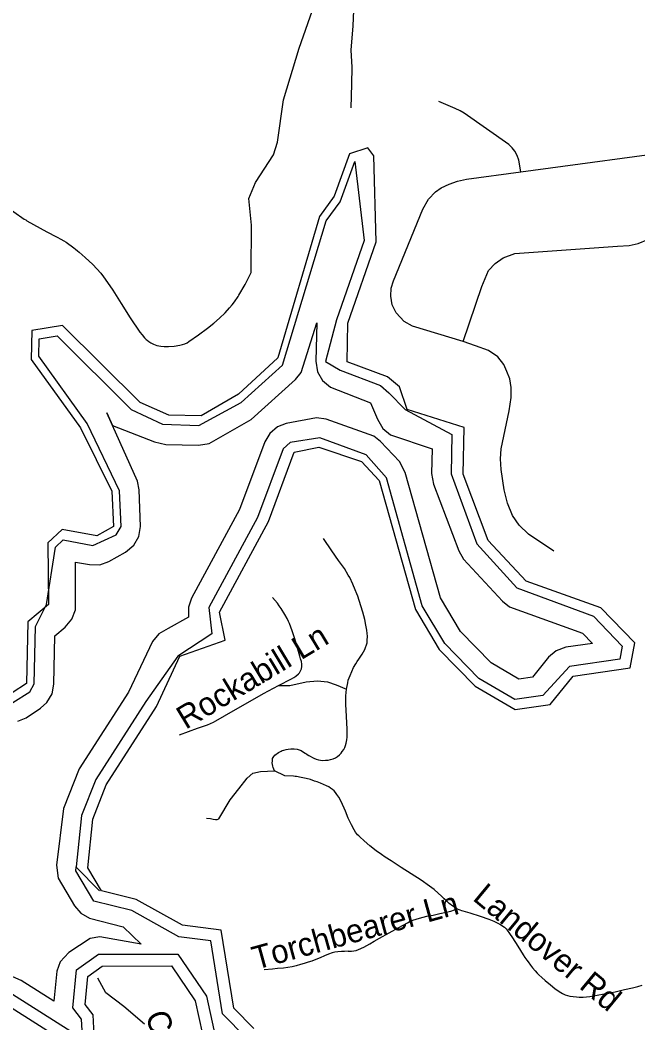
# Model space of a CAD drawing. Extents: x 1383679 to 1536984, y 460658 to 651027.
# Drawn here: x 1388732 to 1391260, y 481592 to 485692 of the extents above; entities that cross this region are included whole.
import ezdxf

# ---------------------------------------------------------------- set-up
doc = ezdxf.new("R2010")
doc.units = 0
for name, color, linetype in [('Exist Hydrographic Bay Label', 7, 'Continuous'), ('Exist Hydrographic Buffer Line', 7, 'Continuous'), ('Exist Hydrographic Misc Water Feature', 7, 'Continuous'), ('Exist Road Non-System Type 51', 7, 'Continuous'), ('Exist Road Non-System Type 51 Label', 7, 'Continuous')]:
    doc.layers.add(name, color=color, linetype=linetype)

msp = doc.modelspace()

# ---------------------------------------------------------------- linework, layer by layer
at = {"layer": 'Exist Hydrographic Bay Label'}
for points in [[(1389688.1, 481568.7), (1389606.1, 481652.4), (1389555.2, 481971.8), (1389397.2, 481991.4), (1389207.2, 482096.9), (1389066.1, 482132.6), (1389010.2, 482225.7), (1389030.2, 482425.5), (1389084.2, 482565.5), (1389290.2, 482886.3), (1389386.2, 483091.2), (1389571.2, 483156.5), (1389548.2, 483271.8), (1389748.1, 483642), (1389854.1, 483925.4), (1389954.1, 483946.4), (1390128.2, 483887.1), (1390201.1, 483810.2), (1390349.1, 483282), (1390446.1, 483119.2), (1390593.1, 482968.5), (1390757.1, 482873.4), (1390900.1, 482893.5), (1390994.1, 483009.7), (1391228, 483044.4), (1391247, 483145.8), (1391108.1, 483289.7), (1390802.1, 483397.7), (1390647.1, 483564.9), (1390544.1, 483836.1), (1390548.1, 484026.4), (1390316.1, 484100), (1390284.1, 484192.5), (1390235.1, 484232.8), (1390070.2, 484295.3), (1390073.1, 484452.8), (1390189.2, 484785.3), (1390179.1, 485136.6), (1390155.2, 485170), (1390079.2, 485145.2), (1390017.2, 484972.5), (1389957.2, 484888.4), (1389787.2, 484310.8), (1389625.2, 484163), (1389473.2, 484074.2), (1389340.2, 484076.9), (1389224.2, 484128.5), (1388906.2, 484443.3), (1388780.2, 484422.9), (1388778.3, 484304.8), (1388980.2, 484025), (1389108.2, 483766.4)], [(1389108.2, 483766.4), (1389114.2, 483621.9), (1389046.2, 483583.8), (1388905.2, 483609.7), (1388846.2, 483555), (1388849.2, 483302.2), (1388764.2, 483231.7), (1388759.2, 482979.1), (1388700.3, 482940.9)], [(1389037.2, 481516.1), (1389031.2, 481624.5), (1388998.2, 481667.8), (1389009.1, 481782.5), (1389068.2, 481824), (1389352.2, 481824.8), (1389449.2, 481681.8), (1389479.1, 481546.5)], [(1387736.3, 481525.7), (1387771.3, 481607.1), (1387924.3, 481722.2), (1388482.2, 481717.6), (1388681.2, 481664.4), (1388928.2, 481508.4)]]:
    msp.add_lwpolyline(points, dxfattribs=at)
at = {"layer": 'Exist Hydrographic Buffer Line'}
msp.add_line((1388961.7, 482229.5), (1389057.5, 482132.5), dxfattribs=at)
for points in [[(1388702.2, 482902.2), (1388772.2, 482945.4), (1388790.5, 482978.1), (1388795.2, 483212.5), (1388840.5, 483302.1), (1388877.7, 483537.6), (1388909, 483566.6), (1389030.3, 483544.3), (1389125, 483586.8), (1389145.5, 483621.7), (1389139.5, 483768), (1389007.4, 484042.6), (1388809.8, 484317.3), (1388811, 484388.6), (1388883.9, 484400.5), (1389187.4, 484099.9), (1389315.2, 484040.2), (1389463.7, 484034.1), (1389636.7, 484128.3), (1389805.5, 484281.1), (1389985, 484870.5), (1390041.1, 484949.1), (1390101.6, 485113.1), (1390140.3, 484791.3), (1390026.7, 484465.8), (1389981.5, 484296.6), (1390041.5, 484260.4), (1390206.2, 484197.6), (1390241.3, 484168.6), (1390307.5, 484099.8), (1390498.9, 483997.1), (1390495.5, 483836.7), (1390601, 483550.5), (1390764.1, 483370.3), (1391077.2, 483254.9), (1391195.2, 483132.7), (1391185.4, 483079.6), (1390979.6, 483049.1), (1390870.2, 482930.7), (1390756.5, 482914.7), (1390609.3, 483000.2), (1390469.5, 483143.6), (1390377.6, 483297.7), (1390231, 483820.8), (1390148.5, 483914.5), (1389958.4, 483984.1), (1389837.3, 483964.4), (1389808.1, 483939.3), (1389703, 483658.5), (1389504.4, 483290.6), (1389516.5, 483182.5), (1389377.6, 483091.1), (1389246.4, 482905.6), (1389041.9, 482587.1), (1388984.2, 482439.8), (1388961.7, 482229.6)], [(1389087.3, 484086.4), (1389110.8, 484034), (1389282.7, 483967.1), (1389329.2, 483956.8), (1389462.1, 483954.1), (1389505.5, 483961.3), (1389677, 484059.3), (1389859.4, 484222), (1389882.5, 484250.7), (1389945.8, 484454.5), (1389941.5, 484297.3), (1389948.7, 484254), (1389969.5, 484217.9), (1390001.5, 484191.2), (1390165.5, 484127.4), (1390194.1, 484060.6), (1390215.5, 484022.6), (1390247.5, 483995.9), (1390417.6, 483938.9), (1390415.5, 483838.4), (1390422.7, 483794.8), (1390526.3, 483522.1), (1390546.5, 483487.5), (1390705.5, 483315.9), (1390733.5, 483293.6), (1391032.8, 483185.8), (1391073.3, 483143.9), (1390964.7, 483127.7), (1390925.5, 483113.4), (1390893.5, 483086.7), (1390827.9, 483005.5), (1390772.8, 482997.8), (1390658.9, 483063.9), (1390533.3, 483192.6), (1390451.7, 483329.5), (1390308, 483842.4), (1390284.4, 483887.1), (1390206.7, 483969.5), (1390179.5, 483990.8), (1389984.1, 484059.8), (1389945.4, 484066.2), (1389820.9, 484042.7), (1389785.5, 484029.2), (1389753.5, 484002.4), (1389733.1, 483967.3), (1389630, 483691.6), (1389433.9, 483328.6), (1389421.3, 483292.4), (1389421.3, 483250.8), (1389337.7, 483204.2), (1389300.5, 483183), (1389273.6, 483151), (1389176.2, 482944.3), (1388974.5, 482630.3), (1388909.5, 482468.6), (1388882, 482237.5), (1388888.7, 482184.5), (1388954.6, 482070.6), (1388980.4, 482040.5), (1389016.5, 482019.7), (1389153.9, 481984.3), (1389227.6, 481914), (1389059.2, 481943.9), (1389018.5, 481936.7), (1388931.5, 481880.6), (1388896.5, 481842.4), (1388882.2, 481803.2), (1388870.3, 481681.3), (1388736.6, 481765.7), (1388703.5, 481780.2)], [(1388958.7, 483281.3), (1388958.5, 483476.2), (1389015.8, 483465.7), (1389058.3, 483465.5), (1389096, 483478.9), (1389164.1, 483517), (1389197.5, 483544.6), (1389218.3, 483580.7), (1389225.5, 483621.7), (1389219.4, 483771.3), (1389212.3, 483807.4), (1389110.8, 484034), (1389087.3, 484086.4)], [(1388723.5, 482825.1), (1388756.8, 482840), (1388815.7, 482878.2), (1388842.5, 482901.8), (1388863.3, 482937.9), (1388870.5, 482976.6), (1388874.5, 483174.3), (1388917.1, 483209.7), (1388944.5, 483242.1), (1388958.7, 483281.3)], [(1389658.3, 481529.7), (1389560.6, 481629.5), (1389512.9, 481928.1), (1389381.8, 481944.3), (1389189.2, 482051.3), (1389034.8, 482090.3), (1388960.2, 482214.4), (1388961.7, 482229.6)], [(1388986, 481561.2), (1388983.5, 481606.9), (1388948, 481653.5), (1388962.9, 481809.5), (1389052.8, 481872.6), (1389377.9, 481873.5), (1389494.6, 481701.4), (1389525, 481564.3)], [(1387688.4, 481537.4), (1387731.7, 481638.2), (1387908.2, 481770.9), (1388488.8, 481766.2), (1388700.9, 481709.4), (1388940.6, 481558)]]:
    msp.add_lwpolyline(points, dxfattribs=at)
at = {"layer": 'Exist Hydrographic Misc Water Feature'}
msp.add_lwpolyline([(1390240.9, 486340.5), (1390239.6, 486276.6), (1390238.9, 486240.5), (1390251.7, 486186), (1390260.5, 486130), (1390266.1, 486106.2), (1390254.9, 486046.5), (1390217.7, 485990.6), (1390158.1, 485917.9), (1390110.7, 485853.2), (1390099.5, 485793.6), (1390092.9, 485669), (1390084.8, 485569), (1390089.4, 485499.2), (1390088, 485429.4), (1390085.9, 485333.5)], dxfattribs=at)
at = {"layer": 'Exist Road Non-System Type 51'}
for points in [[(1388664, 484937.4), (1388749.5, 484878.4), (1388755.9, 484874.6), (1388760.5, 484871.6), (1388841.6, 484826.8), (1388881.4, 484805.6), (1388883.8, 484804.4), (1388899, 484796.6), (1388911.1, 484789.4), (1388920.3, 484783.6), (1388952.8, 484761.2), (1388959.4, 484755.8), (1388967.4, 484748.9), (1388973.8, 484743.4), (1388999, 484721.6), (1389029.7, 484692.1), (1389062.1, 484657), (1389065.1, 484653.6), (1389070.5, 484646), (1389112, 484587.1), (1389145.9, 484533.6), (1389183.3, 484475.2), (1389222.6, 484416.4), (1389231.8, 484404.9), (1389242, 484393), (1389244.6, 484389.8), (1389248.2, 484386.2), (1389252.1, 484382.7), (1389258.7, 484377.6), (1389266.7, 484372.6), (1389277.8, 484367.3), (1389291.8, 484362), (1389307.5, 484358.4), (1389321.3, 484357.2), (1389339.4, 484357.3), (1389363, 484359.3), (1389386.2, 484362.7), (1389396.5, 484365.3), (1389406.8, 484368.9), (1389415.9, 484373), (1389422.9, 484377.2), (1389462.1, 484405.3), (1389499.1, 484432.1), (1389524.4, 484452.5), (1389548.5, 484473), (1389570.6, 484494.5), (1389589.3, 484515.3), (1389600, 484528.2), (1389609.5, 484540.2), (1389624, 484561.2), (1389627.7, 484567.2), (1389652.5, 484611.4), (1389677.6, 484659.9), (1389679.2, 484854.1), (1389668, 484962.4), (1389695.9, 485027.4), (1389768.5, 485141.2), (1389785.3, 485192.6), (1389810.4, 485365.9), (1389874.6, 485577.1), (1389936, 485755.9)], [(1390779.9, 485071.1), (1390772.4, 485119.7), (1390765.6, 485138.9), (1390756, 485156), (1390745.6, 485170.1), (1390731.5, 485183.5), (1390548.1, 485311.2), (1390532.6, 485320.8), (1390511.8, 485330.4), (1390445.8, 485358.7)], [(1390779.9, 485071.1), (1391487.6, 485167.5), (1391529, 485169.7), (1391561.8, 485160.9), (1391603.2, 485130.3)], [(1390545, 484377.7), (1390621.4, 484602.3), (1390647.6, 484667.8), (1390675.9, 484696.2), (1390708.6, 484720.2), (1390756.6, 484737.7), (1391175.6, 484768.2), (1391223.6, 484770.3), (1391260.6, 484779.1), (1391299.9, 484794.3), (1391334.9, 484824.9), (1391603.2, 485130.3)], [(1390545, 484377.7), (1390337.8, 484440.9), (1390303.1, 484460.3), (1390270.1, 484495.5), (1390254.9, 484528.2), (1390248.4, 484563.1), (1390250.5, 484595.8), (1390259.2, 484626.3), (1390379.2, 484918.8), (1390403.4, 484960), (1390431.2, 484989.1), (1390454.6, 485006.6), (1390487.1, 485020.6), (1390522.1, 485033.4), (1390558.1, 485040.9), (1390779.9, 485071.1)], [(1390915.9, 483520.2), (1390811.2, 483590), (1390774.1, 483627.1), (1390745.8, 483666.3), (1390726.1, 483716.6), (1390713, 483771.1), (1390699.9, 483854), (1390697.8, 483897.7), (1390699.9, 483939.1), (1390732.6, 484094), (1390741.4, 484148.6), (1390741.4, 484190), (1390734.9, 484224.9), (1390723.9, 484255.5), (1390710.9, 484283.8), (1390686.4, 484315.8), (1390647.6, 484340.6), (1390595.2, 484360.2), (1390545, 484377.7)], [(1390067.2, 482956.6), (1390072.4, 482982.1), (1390075, 482992.7), (1390082.1, 483012.3), (1390089, 483028.4), (1390096.7, 483044.6), (1390105.6, 483060.5), (1390111.7, 483069.7), (1390117.8, 483078.9), (1390131.2, 483099.7), (1390142.1, 483118.5), (1390145.6, 483126.3), (1390149.6, 483137.9), (1390151.4, 483145.5), (1390152.4, 483155.5), (1390153.2, 483173.4), (1390152.4, 483184.3), (1390151, 483197.4), (1390147.2, 483217.8), (1390142.2, 483241.4), (1390134.2, 483271.9), (1390119.1, 483319.6), (1390113.7, 483336.6), (1390110.2, 483346.1), (1390103.6, 483362.5), (1390093.6, 483385.7), (1390080.6, 483412.6), (1390075, 483422.7), (1390058.9, 483449.4), (1390034.9, 483482.6), (1390007.3, 483522.7), (1389974, 483572.7)], [(1389789.4, 482971.1), (1389842.1, 482998.7), (1389851.7, 483004.2), (1389860.2, 483009.6), (1389871.5, 483019.5), (1389875.1, 483023.6), (1389879.8, 483030.8), (1389883.1, 483039.7), (1389885, 483049.5), (1389884.6, 483059.3), (1389883, 483069.1), (1389880, 483081.2), (1389877.1, 483091.1), (1389855.6, 483162.8), (1389844.7, 483194.7), (1389833.8, 483224.7), (1389830.2, 483232.8), (1389824.6, 483245.5), (1389815.8, 483261.8), (1389800.3, 483286.9), (1389792.8, 483297.2), (1389784.9, 483307.8), (1389764.4, 483331.6)], [(1389789.4, 482971.1), (1389836.1, 482971.1), (1389903.1, 482986.4), (1389948.4, 482990.2), (1389989.8, 482986.4), (1390025.2, 482974.9), (1390067.2, 482956.6)], [(1389384, 482769.9), (1389457.6, 482796.5), (1389498.7, 482810.9), (1389510.9, 482816.5), (1389523.7, 482822), (1389533.5, 482827.1), (1389568.1, 482847.1), (1389728.2, 482939), (1389789.4, 482971.1)], [(1389772.8, 482623.3), (1389767.5, 482636.4), (1389765.8, 482641.5), (1389764.5, 482648.2), (1389764.1, 482654.9), (1389764.2, 482662.3), (1389764.4, 482668.1), (1389765.4, 482672.5), (1389767.1, 482677.1), (1389769.9, 482681.9), (1389774.4, 482687), (1389779.4, 482691), (1389783.4, 482693.8), (1389789.5, 482697.9), (1389794.9, 482700.9), (1389800, 482703.3), (1389804.8, 482705.1), (1389810.8, 482707), (1389820.4, 482709.3), (1389828.7, 482710.8), (1389840, 482712.1), (1389853.7, 482712.5), (1389866, 482711.3), (1389874.1, 482709.1), (1389881.7, 482706), (1389888.1, 482702.2), (1389898.1, 482695.5), (1389901.4, 482693.4), (1389902.4, 482692.7), (1389913.6, 482685.5), (1389934.2, 482674.5), (1389943.4, 482670.6), (1389953, 482668), (1389961.1, 482666.7), (1389971, 482665.4), (1389982.3, 482665.7), (1389993, 482666.7), (1390002.7, 482668.5), (1390013.1, 482671.6), (1390022.1, 482675.8), (1390030.9, 482681.8), (1390038.3, 482687.9), (1390045.4, 482695.2), (1390050.4, 482701.1), (1390056.1, 482709.4), (1390060.7, 482718.4), (1390063.8, 482726), (1390066.6, 482735.3), (1390067.9, 482742), (1390068.9, 482749.7), (1390069.8, 482759.7), (1390069.7, 482792.5), (1390067.8, 482845.2), (1390064.3, 482895), (1390065, 482929.7), (1390067.2, 482956.6)], [(1389495.6, 482429.5), (1389510.8, 482427.3), (1389521.7, 482425.2), (1389531.8, 482424.1), (1389538.6, 482424.3), (1389545.5, 482425.9), (1389591.8, 482504.7), (1389627.3, 482548.6), (1389660.8, 482592.6), (1389684.4, 482613.6), (1389715.9, 482619.4), (1389772.8, 482623.3)], [(1390520.2, 482058.6), (1390519, 482059.2), (1390509.3, 482064.9), (1390502, 482070), (1390487.6, 482080.8), (1390476.3, 482090.9), (1390466.9, 482099.8), (1390456.5, 482109.9), (1390443.1, 482122.9), (1390426.1, 482137.6), (1390407.2, 482151.6), (1390373, 482175), (1390291.1, 482227.3), (1390249.7, 482254.2), (1390225.3, 482269.7), (1390210.1, 482280), (1390189.5, 482295.2), (1390163.4, 482316.1), (1390139.7, 482336.5), (1390121.4, 482353.1), (1390117.3, 482356.7), (1390112.9, 482361.4), (1390108.6, 482366.4), (1390104.4, 482372.4), (1390098.7, 482381.8), (1390088, 482401.6), (1390078.7, 482420.8), (1390075, 482428.9), (1390063.2, 482457.9), (1390045.8, 482497.3), (1390036, 482515), (1390028, 482526.4), (1390022, 482534.1), (1390016.9, 482540.3), (1390010.2, 482546.3), (1390002.5, 482551.8), (1389994.8, 482556.7), (1389985.1, 482561.4), (1389973.8, 482566.3), (1389960.5, 482571.8), (1389948, 482577.1), (1389937.1, 482581), (1389920.3, 482586.6), (1389902.2, 482591.2), (1389882.6, 482595.8), (1389863, 482599.1), (1389857.2, 482600), (1389850.8, 482600.7), (1389814.9, 482602.4), (1389772.8, 482623.3)], [(1390075, 481884.8), (1390087.3, 481885.1), (1390096.9, 481886.2), (1390107.3, 481888.6), (1390116.8, 481892), (1390138.1, 481902.3), (1390150.1, 481909), (1390162.6, 481915.7), (1390180.9, 481926), (1390202.3, 481938.3), (1390281.4, 481982.7), (1390316.4, 482001.8), (1390327.4, 482007.4), (1390338.8, 482011.5), (1390365.4, 482019.8), (1390395.5, 482027.9), (1390421.5, 482032.8), (1390449.3, 482038.9), (1390474.9, 482044.9), (1390494.3, 482048.5), (1390508.9, 482053.8), (1390520.2, 482058.6)], [(1390520.2, 482058.6), (1390526.7, 482055.7), (1390530.9, 482054.1), (1390537.4, 482052.2), (1390543.1, 482050.6), (1390571.8, 482042.1), (1390614.3, 482028), (1390650.2, 482016.2), (1390670.7, 482007.9), (1390684.3, 482001.4), (1390694, 481995.9), (1390700.8, 481991.9), (1390706.5, 481988.2), (1390713.1, 481983.4), (1390719.9, 481976.6), (1390724.6, 481971.4), (1390734.6, 481957.5), (1390747.1, 481939.5), (1390767.6, 481906.5), (1390790, 481869.9), (1390797.2, 481859.4), (1390804.8, 481848.8), (1390810.5, 481841.2), (1390820.1, 481828.5), (1390828.8, 481817.1), (1390839, 481805.1), (1390847.2, 481796.1), (1390854.8, 481788.7), (1390866.8, 481777.7), (1390879.4, 481766.1), (1390901.3, 481747.5), (1390920.2, 481732.6), (1390932.7, 481723.6), (1390943.9, 481716.3), (1390950.5, 481712.2), (1390961.7, 481707.2), (1390970.8, 481704.3), (1390981.6, 481702), (1390994.1, 481700.4), (1391008.4, 481698.5), (1391019, 481697.8), (1391035.8, 481697.8), (1391048.9, 481698.5), (1391063.3, 481700), (1391092.3, 481705.4), (1391121.9, 481711.1), (1391166.6, 481719.8), (1391203.9, 481728.3), (1391236.6, 481736), (1391259.2, 481741.5), (1391276.5, 481746)], [(1390074.6, 481884.8), (1390059.4, 481884.2), (1390046.4, 481883.5), (1390031.7, 481882.6), (1390019.6, 481881.1), (1390009.3, 481878), (1389993.6, 481872.7), (1389978, 481865.9), (1389959.6, 481858.5), (1389942.5, 481851.8), (1389925.3, 481845.2), (1389910.1, 481839.8), (1389894.4, 481834.6), (1389879.6, 481830.4), (1389862, 481825.7), (1389845.6, 481821.7), (1389828.2, 481818.6), (1389810.3, 481816.3), (1389785.5, 481814), (1389764.6, 481811.8), (1389730.4, 481809.3)], [(1389241.1, 481587.1), (1389156.4, 481659.8), (1389083.5, 481715.2), (1389050, 481774.5)]]:
    msp.add_lwpolyline(points, dxfattribs=at)

# ---------------------------------------------------------------- texts
at = {"layer": 'Exist Road Non-System Type 51 Label'}
for s, rotation, p in [('Rockabill Ln', 31.0672, (1389409.8, 482789.8)), ('Landover Rd', 320.4037, (1390579.3, 482097)), ('Torchbearer Ln', 15.4015, (1389696.5, 481808.7)), ('Culross Ln', 288.802, (1389243.6, 481624.1))]:
    msp.add_text(s, height=95, rotation=rotation, dxfattribs=at).set_placement(p)

doc.saveas('drawing.dxf')
